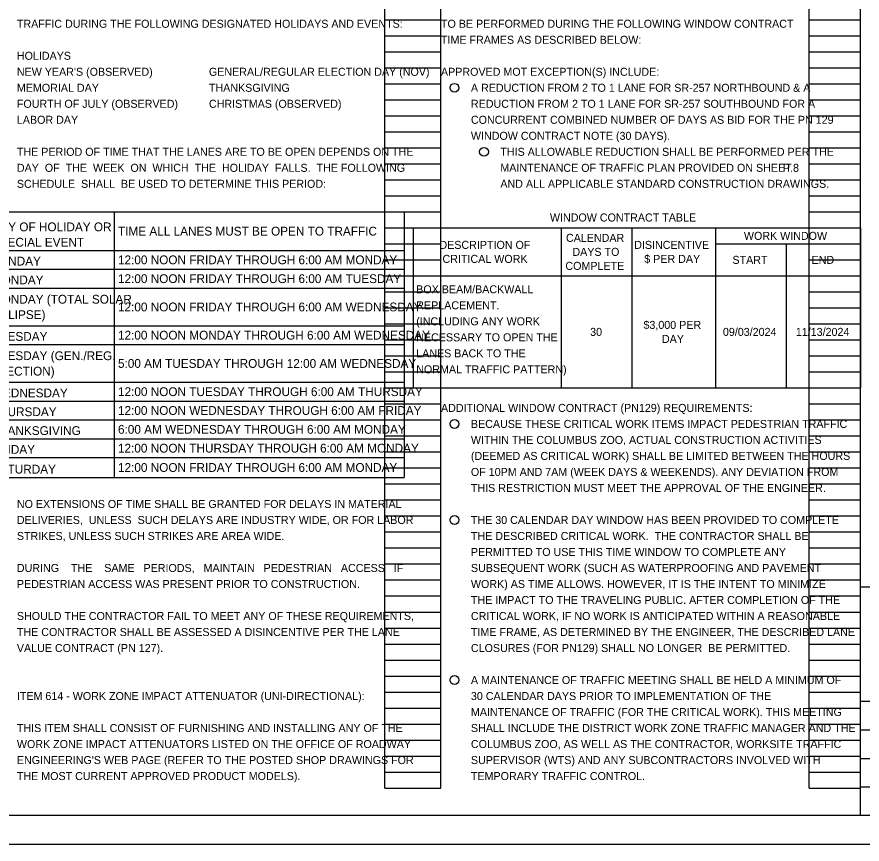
# Model space of a CAD drawing. Extents: x -15.6 to 56.6, y 0 to 56.8.
# Drawn here: x 17.24 to 32.03, y 0 to 14.47 of the extents above; entities that cross this region are included whole.
import ezdxf

# ---------------------------------------------------------------- set-up
doc = ezdxf.new("R2010")
doc.units = 0
for name, color, linetype in [('SH_Border', 7, 'Continuous'), ('SH_Cut_Line', 7, 'Continuous'), ('SH_Data', 7, 'Continuous'), ('SH_Text', 7, 'Continuous')]:
    doc.layers.add(name, color=color, linetype=linetype)

msp = doc.modelspace()

# ---------------------------------------------------------------- linework, layer by layer
at = {"layer": 'SH_Border'}
for p, q in [((32, 0.5), (32, 21.5)), ((32, 4.5), (33.5, 4.5)), ((32, 2.5), (33.5, 2.5)), ((32, 2), (33.5, 2)), ((32, 1.5), (33.5, 1.5)), ((32, 1), (33.5, 1))]:
    msp.add_line(p, q, dxfattribs=at)
msp.add_lwpolyline([(1.5, 21.5), (33.5, 21.5), (33.5, 0.5), (1.5, 0.5)], close=True, dxfattribs=at)
at = {"layer": 'SH_Cut_Line'}
msp.add_lwpolyline([(0, 0), (34, 0), (34, 22), (0, 22)], close=True, dxfattribs=at)
at = {"layer": 'SH_Data'}
for p, q in [((23.68, 0.98), (23.68, 21.14)), ((24.66, 0.98), (24.66, 21.14)), ((31.1, 0.98), (31.1, 21.14)), ((32, 0.98), (32, 21.14)), ((23.68, 14.42), (24.66, 14.42)), ((31.1, 14.42), (32, 14.42)), ((23.68, 14.14), (24.66, 14.14)), ((31.1, 14.14), (32, 14.14)), ((23.68, 13.86), (24.66, 13.86)), ((31.1, 13.86), (32, 13.86)), ((23.68, 13.58), (24.66, 13.58)), ((31.1, 13.58), (32, 13.58)), ((23.68, 13.3), (24.66, 13.3)), ((31.1, 13.3), (32, 13.3)), ((23.68, 13.02), (24.66, 13.02)), ((31.1, 13.02), (32, 13.02)), ((23.68, 12.74), (24.66, 12.74)), ((31.1, 12.74), (32, 12.74)), ((23.68, 12.46), (24.66, 12.46)), ((31.1, 12.46), (32, 12.46)), ((23.68, 12.18), (24.66, 12.18)), ((31.1, 12.18), (32, 12.18)), ((23.68, 11.9), (24.66, 11.9)), ((31.1, 11.9), (32, 11.9)), ((23.68, 11.62), (24.66, 11.62)), ((31.1, 11.62), (32, 11.62)), ((23.68, 11.34), (24.66, 11.34)), ((31.1, 11.34), (32, 11.34)), ((16.736, 11.06), (24.016, 11.06)), ((18.943, 11.06), (18.943, 6.415)), ((23.68, 11.06), (24.66, 11.06)), ((24.016, 11.06), (24.016, 6.415)), ((31.1, 11.06), (32, 11.06)), ((23.68, 10.78), (24.66, 10.78)), ((31.1, 10.78), (32, 10.78)), ((23.68, 10.5), (24.66, 10.5)), ((31.1, 10.5), (32, 10.5)), ((16.736, 10.385), (24.016, 10.385)), ((23.68, 10.22), (24.66, 10.22)), ((31.1, 10.22), (32, 10.22)), ((16.736, 10.055), (24.016, 10.055)), ((23.68, 9.94), (24.66, 9.94)), ((31.1, 9.94), (32, 9.94)), ((16.736, 9.726), (24.016, 9.726)), ((23.68, 9.66), (24.66, 9.66)), ((31.1, 9.66), (32, 9.66)), ((23.68, 9.38), (24.66, 9.38)), ((31.1, 9.38), (32, 9.38)), ((16.736, 9.067), (24.016, 9.067)), ((23.68, 9.1), (24.66, 9.1)), ((31.1, 9.1), (32, 9.1)), ((16.736, 8.738), (24.016, 8.738)), ((23.68, 8.82), (24.66, 8.82)), ((31.1, 8.82), (32, 8.82)), ((23.68, 8.54), (24.66, 8.54)), ((31.1, 8.54), (32, 8.54)), ((23.68, 8.26), (24.66, 8.26)), ((31.1, 8.26), (32, 8.26)), ((16.736, 8.079), (24.016, 8.079)), ((23.68, 7.98), (24.66, 7.98)), ((31.1, 7.98), (32, 7.98)), ((16.736, 7.749), (24.016, 7.749)), ((23.68, 7.7), (24.66, 7.7)), ((31.1, 7.7), (32, 7.7)), ((16.736, 7.42), (24.016, 7.42)), ((23.68, 7.42), (24.66, 7.42)), ((31.1, 7.42), (32, 7.42)), ((23.68, 7.14), (24.66, 7.14)), ((31.1, 7.14), (32, 7.14)), ((16.736, 7.091), (24.016, 7.091)), ((23.68, 6.86), (24.66, 6.86)), ((31.1, 6.86), (32, 6.86)), ((16.736, 6.761), (24.016, 6.761)), ((23.68, 6.58), (24.66, 6.58)), ((31.1, 6.58), (32, 6.58)), ((16.736, 6.415), (24.016, 6.415)), ((23.68, 6.3), (24.66, 6.3)), ((31.1, 6.3), (32, 6.3)), ((23.68, 6.02), (24.66, 6.02)), ((31.1, 6.02), (32, 6.02)), ((23.68, 5.74), (24.66, 5.74)), ((31.1, 5.74), (32, 5.74)), ((23.68, 5.46), (24.66, 5.46)), ((31.1, 5.46), (32, 5.46)), ((23.68, 5.18), (24.66, 5.18)), ((31.1, 5.18), (32, 5.18)), ((23.68, 4.9), (24.66, 4.9)), ((31.1, 4.9), (32, 4.9)), ((23.68, 4.62), (24.66, 4.62)), ((31.1, 4.62), (32, 4.62)), ((23.68, 4.34), (24.66, 4.34)), ((31.1, 4.34), (32, 4.34)), ((23.68, 4.06), (24.66, 4.06)), ((31.1, 4.06), (32, 4.06)), ((23.68, 3.78), (24.66, 3.78)), ((31.1, 3.78), (32, 3.78)), ((23.68, 3.5), (24.66, 3.5)), ((31.1, 3.5), (32, 3.5)), ((23.68, 3.22), (24.66, 3.22)), ((31.1, 3.22), (32, 3.22)), ((23.68, 2.94), (24.66, 2.94)), ((31.1, 2.94), (32, 2.94)), ((23.68, 2.66), (24.66, 2.66)), ((31.1, 2.66), (32, 2.66)), ((23.68, 2.38), (24.66, 2.38)), ((31.1, 2.38), (32, 2.38)), ((23.68, 2.1), (24.66, 2.1)), ((31.1, 2.1), (32, 2.1)), ((23.68, 1.82), (24.66, 1.82)), ((31.1, 1.82), (32, 1.82)), ((23.68, 1.54), (24.66, 1.54)), ((31.1, 1.54), (32, 1.54)), ((23.68, 1.26), (24.66, 1.26)), ((31.1, 1.26), (32, 1.26)), ((23.68, 0.98), (24.66, 0.98)), ((31.1, 0.98), (32, 0.98))]:
    msp.add_line(p, q, dxfattribs=at)
at = {"layer": 'SH_Text'}
for p, q in [((24.176, 10.78), (32, 10.78)), ((24.176, 10.78), (24.176, 7.98)), ((26.762, 10.78), (26.762, 7.98)), ((27.998, 10.78), (27.998, 7.98)), ((29.464, 10.78), (29.464, 7.98)), ((32, 10.78), (32, 7.98)), ((29.464, 10.5), (32, 10.5)), ((30.699, 10.5), (30.699, 7.98)), ((24.176, 9.94), (32, 9.94)), ((24.176, 7.98), (32, 7.98))]:
    msp.add_line(p, q, dxfattribs=at)
for centre in [(24.896, 13.23), (25.412, 12.11), (24.896, 7.35), (24.896, 5.67), (24.896, 2.87)]:
    msp.add_circle(centre, 0.0775, dxfattribs=at)

# ---------------------------------------------------------------- texts
at = {"layer": 'SH_Data'}
for s, height, p in [('LABOR DAY', 0.14, (17.24, 12.6)), ('WINDOW CONTRACT TABLE', 0.14, (26.566, 10.891)), ('DAY OF HOLIDAY OR ', 0.154, (16.802, 10.72)), ('TIME ALL LANES MUST BE OPEN TO TRAFFIC', 0.154, (19.009, 10.645)), ('SPECIAL EVENT', 0.154, (16.802, 10.451)), ('SUNDAY', 0.154, (16.802, 10.121)), ('12:00 NOON FRIDAY THROUGH 6:00 AM MONDAY', 0.154, (19.009, 10.143)), ('MONDAY', 0.154, (16.802, 9.792)), ('12:00 NOON FRIDAY THROUGH 6:00 AM TUESDAY', 0.154, (19.009, 9.814)), ('BOX BEAM/BACKWALL ', 0.14, (24.227, 9.635)), ('MONDAY (TOTAL SOLAR ', 0.154, (16.802, 9.454)), ('12:00 NOON FRIDAY THROUGH 6:00 AM WEDNESDAY', 0.154, (19.009, 9.319)), ('REPLACEMENT.', 0.14, (24.227, 9.355)), ('ECLIPSE)', 0.154, (16.802, 9.185)), ('(INCLUDING ANY WORK', 0.14, (24.227, 9.075)), ('TUESDAY', 0.154, (16.802, 8.804)), ('12:00 NOON MONDAY THROUGH 6:00 AM WEDNESDAY', 0.154, (19.009, 8.825)), ('NECESSARY TO OPEN THE', 0.14, (24.227, 8.795)), ('TUESDAY (GEN./REG. ', 0.154, (16.802, 8.466)), ('LANES BACK TO THE ', 0.14, (24.227, 8.515)), ('5:00 AM TUESDAY THROUGH 12:00 AM WEDNESDAY', 0.154, (19.009, 8.331)), ('ELECTION)', 0.154, (16.802, 8.196)), ('NORMAL TRAFFIC PATTERN)', 0.14, (24.227, 8.235)), ('12:00 NOON TUESDAY THROUGH 6:00 AM THURSDAY', 0.154, (19.009, 7.837)), ('WEDNESDAY', 0.154, (16.802, 7.815)), ('THURSDAY', 0.154, (16.802, 7.486)), ('12:00 NOON WEDNESDAY THROUGH 6:00 AM FRIDAY', 0.154, (19.009, 7.508)), ('THANKSGIVING', 0.154, (16.802, 7.156)), ('6:00 AM WEDNESDAY THROUGH 6:00 AM MONDAY', 0.154, (19.009, 7.178)), ('FRIDAY', 0.154, (16.802, 6.827)), ('12:00 NOON THURSDAY THROUGH 6:00 AM MONDAY', 0.154, (19.009, 6.849)), ('12:00 NOON FRIDAY THROUGH 6:00 AM MONDAY', 0.154, (19.009, 6.511)), ('SATURDAY', 0.154, (16.802, 6.481))]:
    msp.add_text(s, height=height, dxfattribs=at).set_placement(p)
at = {"layer": 'SH_Text'}
for s, p in [('TRAFFIC DURING THE FOLLOWING DESIGNATED HOLIDAYS AND EVENTS:', (17.24, 14.28)), ('TO BE PERFORMED DURING THE FOLLOWING WINDOW CONTRACT ', (24.66, 14.28)), ('TIME FRAMES AS DESCRIBED BELOW:', (24.66, 14)), ('HOLIDAYS', (17.24, 13.72)), ("NEW YEAR'S (OBSERVED)", (17.24, 13.44)), ('GENERAL/REGULAR ELECTION DAY (NOV)', (20.6, 13.44)), ('APPROVED MOT EXCEPTION(S) INCLUDE: ', (24.66, 13.44)), ('MEMORIAL DAY', (17.24, 13.16)), ('THANKSGIVING', (20.6, 13.16)), ('A REDUCTION FROM 2 TO 1 LANE FOR SR-257 NORTHBOUND & A ', (25.184, 13.16)), ('FOURTH OF JULY (OBSERVED)', (17.24, 12.88)), ('CHRISTMAS (OBSERVED)', (20.6, 12.88)), ('REDUCTION FROM 2 TO 1 LANE FOR SR-257 SOUTHBOUND FOR A ', (25.184, 12.88)), ('CONCURRENT COMBINED NUMBER OF DAYS AS BID FOR THE PN 129 ', (25.184, 12.6)), ('WINDOW CONTRACT NOTE (30 DAYS).', (25.184, 12.32)), ('THE PERIOD OF TIME THAT THE LANES ARE TO BE OPEN DEPENDS ON THE', (17.24, 12.04)), ('THIS ALLOWABLE REDUCTION SHALL BE PERFORMED PER THE', (25.699, 12.04)), ('DAY  OF  THE  WEEK  ON  WHICH  THE  HOLIDAY  FALLS.  THE FOLLOWING', (17.24, 11.76)), ('MAINTENANCE OF TRAFFIC PLAN PROVIDED ON SHEET ', (25.699, 11.76)), ('P.8', (30.643, 11.76)), ('SCHEDULE  SHALL  BE USED TO DETERMINE THIS PERIOD:', (17.24, 11.48)), ('AND ALL APPLICABLE STANDARD CONSTRUCTION DRAWINGS.', (25.699, 11.48)), ('CALENDAR ', (26.847, 10.535)), ('WORK WINDOW', (29.96, 10.57)), ('DESCRIPTION OF ', (24.633, 10.412)), ('DISINCENTIVE ', (28.041, 10.412)), ('DAYS TO ', (26.96, 10.29)), ('CRITICAL WORK', (24.687, 10.167)), ('$ PER DAY', (28.217, 10.167)), ('START', (29.76, 10.15)), ('END', (31.144, 10.15)), ('COMPLETE', (26.837, 10.045)), ('30', (27.27, 8.89)), ('$3,000 PER ', (28.203, 9.012)), ('09/03/2024', (29.593, 8.89)), ('11/13/2024', (30.869, 8.89)), ('DAY', (28.526, 8.767)), ('ADDITIONAL WINDOW CONTRACT (PN129) REQUIREMENTS: ', (24.66, 7.56)), ('BECAUSE THESE CRITICAL WORK ITEMS IMPACT PEDESTRIAN TRAFFIC  ', (25.184, 7.28)), ('WITHIN THE COLUMBUS ZOO, ACTUAL CONSTRUCTION ACTIVITIES ', (25.184, 7)), ('(DEEMED AS CRITICAL WORK) SHALL BE LIMITED BETWEEN THE HOURS ', (25.184, 6.72)), ('OF 10PM AND 7AM (WEEK DAYS & WEEKENDS). ANY DEVIATION FROM ', (25.184, 6.44)), ('THIS RESTRICTION MUST MEET THE APPROVAL OF THE ENGINEER. ', (25.184, 6.16)), ('NO EXTENSIONS OF TIME SHALL BE GRANTED FOR DELAYS IN MATERIAL', (17.24, 5.88)), ('DELIVERIES,  UNLESS  SUCH DELAYS ARE INDUSTRY WIDE, OR FOR LABOR', (17.24, 5.6)), ('THE 30 CALENDAR DAY WINDOW HAS BEEN PROVIDED TO COMPLETE ', (25.184, 5.6)), ('STRIKES, UNLESS SUCH STRIKES ARE AREA WIDE.', (17.24, 5.32)), ('THE DESCRIBED CRITICAL WORK.  THE CONTRACTOR SHALL BE ', (25.184, 5.32)), ('PERMITTED TO USE THIS TIME WINDOW TO COMPLETE ANY ', (25.184, 5.04)), ('DURING    THE    SAME   PERIODS,   MAINTAIN   PEDESTRIAN   ACCESS   IF', (17.24, 4.76)), ('SUBSEQUENT WORK (SUCH AS WATERPROOFING AND PAVEMENT ', (25.184, 4.76)), ('PEDESTRIAN ACCESS WAS PRESENT PRIOR TO CONSTRUCTION.', (17.24, 4.48)), ('WORK) AS TIME ALLOWS. HOWEVER, IT IS THE INTENT TO MINIMIZE ', (25.184, 4.48)), ('THE IMPACT TO THE TRAVELING PUBLIC. AFTER COMPLETION OF THE ', (25.184, 4.2)), ('SHOULD THE CONTRACTOR FAIL TO MEET ANY OF THESE REQUIREMENTS,', (17.24, 3.92)), ('CRITICAL WORK, IF NO WORK IS ANTICIPATED WITHIN A REASONABLE ', (25.184, 3.92)), ('THE CONTRACTOR SHALL BE ASSESSED A DISINCENTIVE PER THE LANE', (17.24, 3.64)), ('TIME FRAME, AS DETERMINED BY THE ENGINEER, THE DESCRIBED LANE ', (25.184, 3.64)), ('VALUE CONTRACT (PN 127).', (17.24, 3.36)), ('CLOSURES (FOR PN129) SHALL NO LONGER  BE PERMITTED. ', (25.184, 3.36)), ('A MAINTENANCE OF TRAFFIC MEETING SHALL BE HELD A MINIMUM OF ', (25.184, 2.8)), ('ITEM 614 - WORK ZONE IMPACT ATTENUATOR (UNI-DIRECTIONAL):', (17.24, 2.52)), ('30 CALENDAR DAYS PRIOR TO IMPLEMENTATION OF THE ', (25.184, 2.52)), ('MAINTENANCE OF TRAFFIC (FOR THE CRITICAL WORK). THIS MEETING ', (25.184, 2.24)), ('THIS ITEM SHALL CONSIST OF FURNISHING AND INSTALLING ANY OF THE', (17.24, 1.96)), ('SHALL INCLUDE THE DISTRICT WORK ZONE TRAFFIC MANAGER AND THE ', (25.184, 1.96)), ('WORK ZONE IMPACT ATTENUATORS LISTED ON THE OFFICE OF ROADWAY', (17.24, 1.68)), ('COLUMBUS ZOO, AS WELL AS THE CONTRACTOR, WORKSITE TRAFFIC ', (25.184, 1.68)), ("ENGINEERING'S WEB PAGE (REFER TO THE POSTED SHOP DRAWINGS FOR", (17.24, 1.4)), ('SUPERVISOR (WTS) AND ANY SUBCONTRACTORS INVOLVED WITH ', (25.184, 1.4)), ('THE MOST CURRENT APPROVED PRODUCT MODELS).', (17.24, 1.12)), ('TEMPORARY TRAFFIC CONTROL. ', (25.184, 1.12))]:
    msp.add_text(s, height=0.14, dxfattribs=at).set_placement(p)

doc.saveas('drawing.dxf')
